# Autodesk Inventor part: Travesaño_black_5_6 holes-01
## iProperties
Created: 2008-01
Part Number: Travesaño_black_5_6 holes-01
Document SubType Name: Modeling
Designer: eruiz-tagle
Mass: 1.07259 g
Surface Area: 20.3811 cm^2
Volume: 1.07259 cm^3
Density: 1 g/cm^3
Author: eruiz-tagle
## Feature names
1. Extrusion2
2. Fillet4
3. Fillet5
4. Hole2
5. Rectangular Pattern2
6. Rectangular Pattern3
7. Fillet6
8. Mirror3
